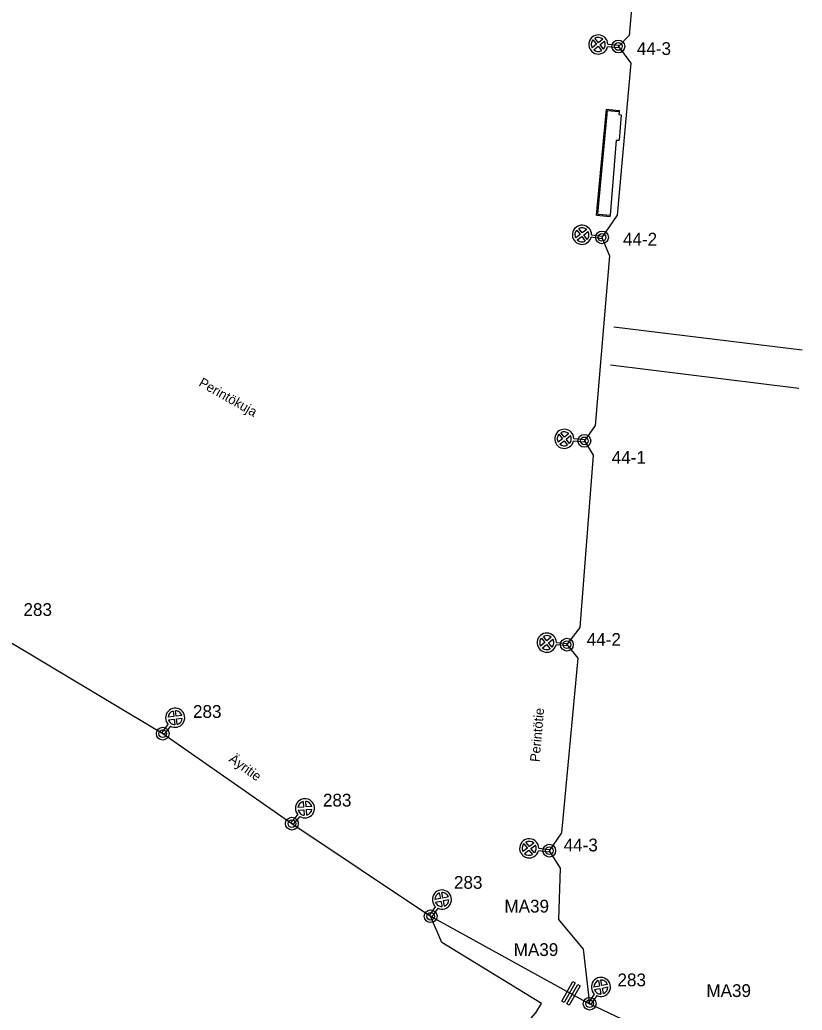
# Model space of a CAD drawing. Extents: x 25497851 to 25498523, y 6686544 to 6687372.
# Drawn here: x 25498113.5 to 25498297.2, y 6686878 to 6687110.6 of the extents above; entities that cross this region are included whole.
import ezdxf

# ---------------------------------------------------------------- set-up
doc = ezdxf.new("R2010")
doc.units = 0
for name, color, linetype in [('AP_Rajapinta', 7, 'Continuous'), ('AP_Reunakivi', 7, 'Continuous'), ('EL_CABLE_MAA', 7, 'Continuous'), ('KAAPELI', 7, 'Continuous'), ('KEYGWT_ANNOTATION', 7, 'Continuous'), ('Level 63', 7, 'Continuous'), ('MUU_UV-SUUNNITELMASYMBOLI', 7, 'Continuous'), ('PYLVAS', 7, 'Continuous'), ('TEKSTI_SUUNNITELMA-ALUE', 7, 'Continuous'), ('TieAlue_ajorata', 7, 'Continuous'), ('VALAISIN', 7, 'Continuous')]:
    doc.layers.add(name, color=color, linetype=linetype)

msp = doc.modelspace()

# ---------------------------------------------------------------- linework, layer by layer
at = {"layer": 'AP_Rajapinta'}
for p, q in [((25498249.28, 6687064.99), (25498251.54, 6687089.29)), ((25498251.54, 6687089.29), (25498254.27, 6687089.03)), ((25498254.75, 6687088.29), (25498254.23, 6687082.31)), ((25498249.28, 6687064.99), (25498252.2, 6687064.73))]:
    msp.add_line(p, q, dxfattribs=at)
for points in [[(25498251.26, 6687089.61), (25498254.3, 6687089.33), (25498254.27, 6687089.03)], [(25498254.27, 6687089.03), (25498254.22, 6687088.34), (25498254.75, 6687088.29)], [(25498252.2, 6687064.73), (25498253.65, 6687082.36), (25498254.23, 6687082.31)], [(25498248.96, 6687064.72), (25498252.17, 6687064.42), (25498252.2, 6687064.73)]]:
    msp.add_lwpolyline(points, dxfattribs=at)
at = {"layer": 'AP_Reunakivi'}
msp.add_line((25498248.96, 6687064.72), (25498251.26, 6687089.61), dxfattribs=at)
at = {"layer": 'EL_CABLE_MAA'}
for points in [[(25498231.88, 6686874.15), (25498234.67, 6686877.37), (25498236.01, 6686879.59), (25498212.63, 6686893.9), (25498209.99, 6686900.07)], [(25498290.21, 6686859.18), (25498247.33, 6686879.52)]]:
    msp.add_lwpolyline(points, dxfattribs=at)
at = {"layer": 'KAAPELI'}
for p, q in [((25498107.28, 6686966.85), (25498147.08, 6686942.96)), ((25498147.08, 6686942.96), (25498177.4, 6686921.82)), ((25498177.4, 6686921.82), (25498209.99, 6686900.07)), ((25498209.99, 6686900.07), (25498247.33, 6686879.52))]:
    msp.add_line(p, q, dxfattribs=at)
for points in [[(25498258.33, 6687154.24), (25498260.46, 6687150.68), (25498256.59, 6687106.94), (25498254.07, 6687104.33)], [(25498254.07, 6687104.33), (25498257, 6687100.45), (25498253.77, 6687064.73), (25498250.22, 6687059.49)], [(25498250.22, 6687059.49), (25498251.96, 6687055.15), (25498248.64, 6687015.33), (25498246.09, 6687011.72)], [(25498246.09, 6687011.72), (25498248.18, 6687008.34), (25498245.03, 6686967.87), (25498241.98, 6686963.86)], [(25498241.98, 6686963.86), (25498244.55, 6686960.66), (25498240.72, 6686919.7), (25498237.84, 6686915.47)], [(25498237.84, 6686915.47), (25498240.38, 6686911.4), (25498239.99, 6686899.35), (25498245.81, 6686892.35), (25498247.33, 6686879.52)]]:
    msp.add_lwpolyline(points, dxfattribs=at)
at = {"layer": 'MUU_UV-SUUNNITELMASYMBOLI'}
for p, q in [((25498240.82, 6686880.13), (25498243.37, 6686884.72)), ((25498243.89, 6686884.43), (25498241.35, 6686879.84)), ((25498242.01, 6686879.47), (25498244.56, 6686884.06)), ((25498245.09, 6686883.76), (25498242.54, 6686879.17)), ((25498243.37, 6686884.72), (25498243.89, 6686884.43)), ((25498244.56, 6686884.06), (25498245.09, 6686883.76)), ((25498241.35, 6686879.84), (25498240.82, 6686880.13)), ((25498242.54, 6686879.17), (25498242.01, 6686879.47))]:
    msp.add_line(p, q, dxfattribs=at)
at = {"layer": 'PYLVAS'}
for centre, radius in [((25498254.07, 6687104.33), 1.5), ((25498254.07, 6687104.33), 0.9), ((25498250.22, 6687059.49), 1.5), ((25498250.22, 6687059.49), 0.9), ((25498246.09, 6687011.72), 1.5), ((25498246.09, 6687011.72), 0.9), ((25498241.98, 6686963.86), 1.5), ((25498241.98, 6686963.86), 0.9), ((25498147.08, 6686942.96), 1.5), ((25498147.08, 6686942.96), 0.9), ((25498177.4, 6686921.82), 1.5), ((25498177.4, 6686921.82), 0.9), ((25498237.84, 6686915.47), 1.5), ((25498237.84, 6686915.47), 0.9), ((25498209.99, 6686900.07), 1.5), ((25498209.99, 6686900.07), 0.9), ((25498247.33, 6686879.52), 1.5), ((25498247.33, 6686879.52), 0.9)]:
    msp.add_circle(centre, radius, dxfattribs=at)
at = {"layer": 'TieAlue_ajorata'}
for p, q in [((25498252.97, 6687038.5), (25498297.24, 6687033.1)), ((25498252.2, 6687029.53), (25498296.47, 6687024.12))]:
    msp.add_line(p, q, dxfattribs=at)
at = {"layer": 'VALAISIN'}
for p, q in [((25498249.4, 6687105.22), (25498248.56, 6687106.25)), ((25498248.93, 6687104.85), (25498247.91, 6687104.01)), ((25498248.1, 6687105.87), (25498248.93, 6687104.85)), ((25498248.29, 6687103.55), (25498249.31, 6687104.38)), ((25498249.31, 6687104.38), (25498250.15, 6687103.36)), ((25498250.42, 6687106.06), (25498249.4, 6687105.22)), ((25498249.78, 6687104.76), (25498250.8, 6687105.59)), ((25498250.61, 6687103.73), (25498249.78, 6687104.76)), ((25498254.04, 6687104.02), (25498251.54, 6687104.28)), ((25498251.6, 6687104.87), (25498254.1, 6687104.62)), ((25498254.1, 6687104.62), (25498254.04, 6687104.02)), ((25498245.1, 6687060.17), (25498244.05, 6687059.37)), ((25498244.3, 6687061.22), (25498245.1, 6687060.17)), ((25498244.41, 6687058.89), (25498245.47, 6687059.69)), ((25498245.58, 6687060.53), (25498244.78, 6687061.59)), ((25498245.47, 6687059.69), (25498246.27, 6687058.64)), ((25498246.63, 6687061.34), (25498245.58, 6687060.53)), ((25498245.94, 6687060.06), (25498247, 6687060.86)), ((25498246.74, 6687059), (25498245.94, 6687060.06)), ((25498247.77, 6687060.11), (25498250.26, 6687059.77)), ((25498250.26, 6687059.77), (25498250.18, 6687059.18)), ((25498250.18, 6687059.18), (25498247.69, 6687059.52)), ((25498240.11, 6687013.25), (25498240.95, 6687012.23)), ((25498241.41, 6687012.61), (25498240.57, 6687013.63)), ((25498242.44, 6687013.44), (25498241.41, 6687012.61)), ((25498240.95, 6687012.23), (25498239.92, 6687011.39)), ((25498240.3, 6687010.93), (25498241.33, 6687011.76)), ((25498241.33, 6687011.76), (25498242.16, 6687010.74)), ((25498241.79, 6687012.14), (25498242.81, 6687012.98)), ((25498242.63, 6687011.12), (25498241.79, 6687012.14)), ((25498246.05, 6687011.41), (25498243.56, 6687011.66)), ((25498243.62, 6687012.26), (25498246.11, 6687012.01)), ((25498246.11, 6687012.01), (25498246.05, 6687011.41)), ((25498236.84, 6686964.37), (25498235.81, 6686963.54)), ((25498236, 6686965.4), (25498236.84, 6686964.37)), ((25498237.3, 6686964.75), (25498236.47, 6686965.78)), ((25498238.33, 6686965.59), (25498237.3, 6686964.75)), ((25498237.68, 6686964.29), (25498238.71, 6686965.12)), ((25498238.52, 6686963.26), (25498237.68, 6686964.29)), ((25498239.51, 6686964.4), (25498242.01, 6686964.14)), ((25498236.19, 6686963.07), (25498237.22, 6686963.91)), ((25498237.22, 6686963.91), (25498238.05, 6686962.88)), ((25498241.95, 6686963.55), (25498239.45, 6686963.8)), ((25498242.01, 6686964.14), (25498241.95, 6686963.55)), ((25498149.5, 6686948.27), (25498149.66, 6686946.96)), ((25498150.25, 6686947.03), (25498150.09, 6686948.34)), ((25498149.66, 6686946.96), (25498148.35, 6686946.79)), ((25498148.42, 6686946.2), (25498149.73, 6686946.36)), ((25498149.73, 6686946.36), (25498149.89, 6686945.05)), ((25498151.57, 6686947.19), (25498150.25, 6686947.03)), ((25498150.33, 6686946.43), (25498151.64, 6686946.59)), ((25498150.49, 6686945.12), (25498150.33, 6686946.43)), ((25498146.84, 6686943.14), (25498148.38, 6686945.12)), ((25498148.86, 6686944.75), (25498147.31, 6686942.77)), ((25498147.31, 6686942.77), (25498146.84, 6686943.14)), ((25498180.75, 6686925.75), (25498180.65, 6686927.07)), ((25498180.15, 6686925.7), (25498178.84, 6686925.59)), ((25498178.88, 6686925), (25498180.2, 6686925.1)), ((25498180.05, 6686927.02), (25498180.15, 6686925.7)), ((25498180.2, 6686925.1), (25498180.31, 6686923.78)), ((25498182.07, 6686925.85), (25498180.75, 6686925.75)), ((25498180.8, 6686925.15), (25498182.12, 6686925.25)), ((25498180.9, 6686923.83), (25498180.8, 6686925.15)), ((25498177.17, 6686922.01), (25498178.8, 6686923.92)), ((25498179.26, 6686923.53), (25498177.63, 6686921.62)), ((25498177.63, 6686921.62), (25498177.17, 6686922.01)), ((25498232.71, 6686916.08), (25498231.67, 6686915.26)), ((25498231.89, 6686917.12), (25498232.71, 6686916.08)), ((25498232.04, 6686914.79), (25498233.08, 6686915.61)), ((25498233.18, 6686916.45), (25498232.36, 6686917.49)), ((25498233.08, 6686915.61), (25498233.89, 6686914.57)), ((25498234.22, 6686917.26), (25498233.18, 6686916.45)), ((25498233.55, 6686915.98), (25498234.59, 6686916.79)), ((25498234.37, 6686914.94), (25498233.55, 6686915.98)), ((25498237.8, 6686915.16), (25498235.31, 6686915.46)), ((25498235.38, 6686916.06), (25498237.87, 6686915.76)), ((25498237.87, 6686915.76), (25498237.8, 6686915.16)), ((25498212.29, 6686904.23), (25498210.99, 6686903.98)), ((25498212.03, 6686905.53), (25498212.29, 6686904.23)), ((25498212.88, 6686904.35), (25498212.62, 6686905.65)), ((25498214.18, 6686904.6), (25498212.88, 6686904.35)), ((25498212.99, 6686903.76), (25498214.29, 6686904.01)), ((25498209.74, 6686900.23), (25498211.15, 6686902.32)), ((25498211.64, 6686901.98), (25498210.24, 6686899.9)), ((25498211.11, 6686903.39), (25498212.4, 6686903.65)), ((25498212.4, 6686903.65), (25498212.66, 6686902.35)), ((25498213.25, 6686902.46), (25498212.99, 6686903.76)), ((25498210.24, 6686899.9), (25498209.74, 6686900.23)), ((25498249.62, 6686883.69), (25498248.32, 6686883.44)), ((25498248.44, 6686882.85), (25498249.74, 6686883.11)), ((25498249.37, 6686884.99), (25498249.62, 6686883.69)), ((25498249.74, 6686883.11), (25498249.99, 6686881.81)), ((25498250.21, 6686883.81), (25498249.95, 6686885.11)), ((25498251.51, 6686884.07), (25498250.21, 6686883.81)), ((25498250.33, 6686883.22), (25498251.62, 6686883.48)), ((25498250.58, 6686881.92), (25498250.33, 6686883.22)), ((25498247.08, 6686879.69), (25498248.48, 6686881.77)), ((25498248.98, 6686881.44), (25498247.58, 6686879.36)), ((25498247.58, 6686879.36), (25498247.08, 6686879.69))]:
    msp.add_line(p, q, dxfattribs=at)
for centre, radius, start, end in [((25498249.36, 6687104.8), 2.25, 1.8287, 174.1665), ((25498249.36, 6687104.8), 1.65, 49.6422, 118.6908), ((25498249.36, 6687104.8), 2.25, 174.1665, 346.5042), ((25498249.36, 6687104.8), 1.65, 139.6422, 174.1665), ((25498249.36, 6687104.8), 1.65, 174.1665, 208.6908), ((25498249.36, 6687104.8), 1.65, 319.6422, 354.1665), ((25498249.36, 6687104.8), 1.65, 354.1665, 28.6908), ((25498249.36, 6687104.8), 1.65, 229.6422, 298.6908), ((25498245.52, 6687060.11), 2.25, 359.9115, 172.2492), ((25498245.52, 6687060.11), 2.25, 172.2492, 344.587), ((25498245.52, 6687060.11), 1.65, 172.2492, 206.7736), ((25498245.52, 6687060.11), 1.65, 137.7249, 172.2492), ((25498245.52, 6687060.11), 1.65, 47.7249, 116.7736), ((25498245.52, 6687060.11), 1.65, 317.7249, 352.2492), ((25498245.52, 6687060.11), 1.65, 352.2492, 26.7736), ((25498245.52, 6687060.11), 1.65, 227.7249, 296.7736), ((25498241.37, 6687012.19), 2.25, 1.8898, 174.2275), ((25498241.37, 6687012.19), 1.65, 139.7032, 174.2275), ((25498241.37, 6687012.19), 1.65, 49.7032, 118.7518), ((25498241.37, 6687012.19), 2.25, 174.2275, 346.5652), ((25498241.37, 6687012.19), 1.65, 174.2275, 208.7518), ((25498241.37, 6687012.19), 1.65, 229.7032, 298.7518), ((25498241.37, 6687012.19), 1.65, 319.7032, 354.2275), ((25498241.37, 6687012.19), 1.65, 354.2275, 28.7518), ((25498237.26, 6686964.33), 2.25, 1.8054, 174.1431), ((25498237.26, 6686964.33), 2.25, 174.1431, 346.4809), ((25498237.26, 6686964.33), 1.65, 174.1431, 208.6674), ((25498237.26, 6686964.33), 1.65, 139.6188, 174.1431), ((25498237.26, 6686964.33), 1.65, 49.6188, 118.6674), ((25498237.26, 6686964.33), 1.65, 354.1431, 28.6674), ((25498237.26, 6686964.33), 1.65, 229.6188, 298.6674), ((25498237.26, 6686964.33), 1.65, 319.6188, 354.1431), ((25498149.99, 6686946.69), 2.25, 52.004, 224.3417), ((25498149.99, 6686946.69), 1.65, 107.4797, 176.5283), ((25498149.99, 6686946.69), 2.25, 239.6662, 52.004), ((25498149.99, 6686946.69), 1.65, 52.004, 86.5283), ((25498149.99, 6686946.69), 1.65, 17.4797, 52.004), ((25498149.99, 6686946.69), 1.65, 197.4797, 232.004), ((25498149.99, 6686946.69), 1.65, 287.4797, 356.5283), ((25498149.99, 6686946.69), 1.65, 232.004, 266.5283), ((25498180.48, 6686925.42), 2.25, 49.5556, 221.8933), ((25498180.48, 6686925.42), 2.25, 237.2178, 49.5556), ((25498180.48, 6686925.42), 1.65, 49.5556, 84.0799), ((25498180.48, 6686925.42), 1.65, 105.0313, 174.0799), ((25498180.48, 6686925.42), 1.65, 195.0313, 229.5556), ((25498180.48, 6686925.42), 1.65, 285.0313, 354.0799), ((25498180.48, 6686925.42), 1.65, 15.0313, 49.5556), ((25498180.48, 6686925.42), 1.65, 229.5556, 264.0799), ((25498233.13, 6686916.03), 2.25, 0.7488, 173.0866), ((25498233.13, 6686916.03), 2.25, 173.0866, 345.4243), ((25498233.13, 6686916.03), 1.65, 173.0866, 207.6109), ((25498233.13, 6686916.03), 1.65, 138.5623, 173.0866), ((25498233.13, 6686916.03), 1.65, 48.5623, 117.6109), ((25498233.13, 6686916.03), 1.65, 318.5623, 353.0866), ((25498233.13, 6686916.03), 1.65, 353.0866, 27.6109), ((25498233.13, 6686916.03), 1.65, 228.5623, 297.6109), ((25498212.64, 6686904), 2.25, 56.0415, 228.3793), ((25498212.64, 6686904), 1.65, 111.5172, 180.5658), ((25498212.64, 6686904), 2.25, 243.7038, 56.0415), ((25498212.64, 6686904), 1.65, 56.0415, 90.5658), ((25498212.64, 6686904), 1.65, 291.5172, 0.5658), ((25498212.64, 6686904), 1.65, 21.5172, 56.0415), ((25498212.64, 6686904), 1.65, 201.5172, 236.0415), ((25498212.64, 6686904), 1.65, 236.0415, 270.5658), ((25498249.97, 6686883.46), 2.25, 56.1117, 228.4495), ((25498249.97, 6686883.46), 2.25, 243.774, 56.1117), ((25498249.97, 6686883.46), 1.65, 111.5874, 180.6361), ((25498249.97, 6686883.46), 1.65, 201.5874, 236.1117), ((25498249.97, 6686883.46), 1.65, 56.1117, 90.6361), ((25498249.97, 6686883.46), 1.65, 291.5874, 0.6361), ((25498249.97, 6686883.46), 1.65, 21.5874, 56.1117), ((25498249.97, 6686883.46), 1.65, 236.1117, 270.6361)]:
    msp.add_arc(centre, radius, start, end, dxfattribs=at)

# ---------------------------------------------------------------- texts
at = {"layer": 'KEYGWT_ANNOTATION'}
for s, p in [('44-3', (25498258.41, 6687102.34)), ('44-2', (25498255.15, 6687057.58)), ('44-1', (25498252.51, 6687006.33)), ('283', (25498114.37, 6686970.6)), ('44-2', (25498246.64, 6686963.58)), ('283', (25498154.18, 6686946.66)), ('283', (25498184.69, 6686925.84)), ('44-3', (25498241.22, 6686915.31)), ('283', (25498215.46, 6686906.52)), ('MA39', (25498227.31, 6686900.94)), ('MA39', (25498229.49, 6686890.74)), ('283', (25498253.86, 6686883.63)), ('MA39', (25498274.74, 6686881.11))]:
    msp.add_text(s, height=3, dxfattribs=at).set_placement(p)
at = {"layer": 'Level 63'}
msp.add_text('(C) KEYPRO 2000', height=0.0001, rotation=124.2, dxfattribs=at).set_placement((25498211.94, 6686902.67))
at = {"layer": 'TEKSTI_SUUNNITELMA-ALUE'}
for s, rotation, p in [('Perintökuja', 330.3502, (25498155.34, 6687024.74)), ('Perintötie', 84.8782, (25498235.54, 6686936.24)), ('Äyritie', 324.0004, (25498162.43, 6686936.58))]:
    msp.add_text(s, height=2.25, rotation=rotation, dxfattribs=at).set_placement(p)

doc.saveas('drawing.dxf')
